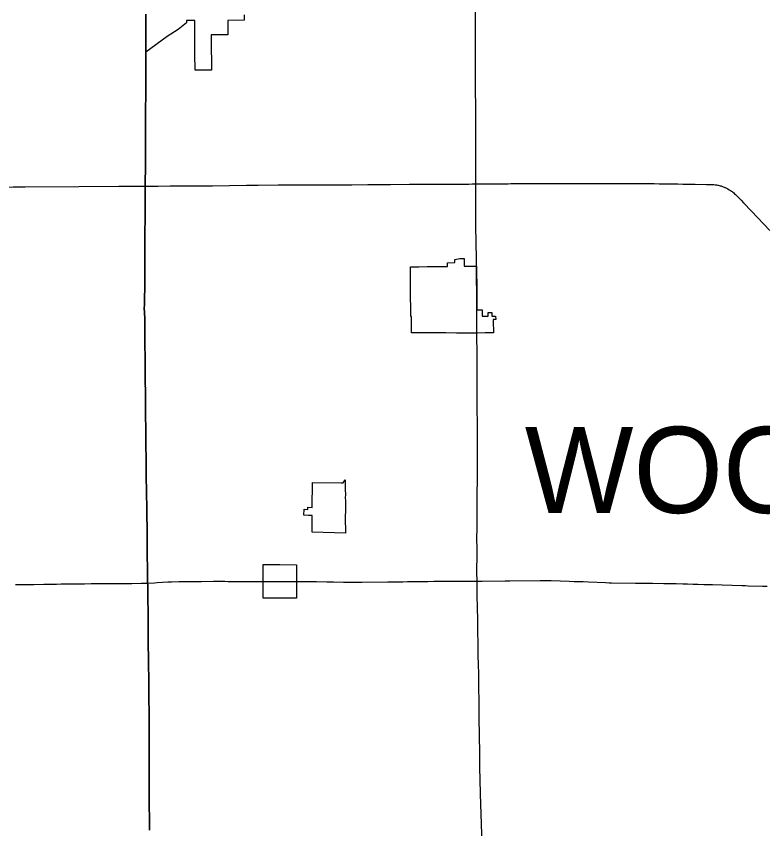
# Model space of a CAD drawing. Extents: x -786946 to -767280, y 417139 to 426807.
# Drawn here: x -778504 to -776473, y 420527 to 422738 of the extents above; entities that cross this region are included whole.
import ezdxf

# ---------------------------------------------------------------- set-up
doc = ezdxf.new("R2010")
doc.units = 0
for name, color, linetype in [('DV_X_Corp_Line', 7, 'Continuous'), ('DV_X_County_Line', 7, 'Continuous'), ('GM_X_State_Route', 7, 'Continuous'), ('SH_Text', 7, 'Continuous')]:
    doc.layers.add(name, color=color, linetype=linetype)

msp = doc.modelspace()

# ---------------------------------------------------------------- linework, layer by layer
at = {"layer": 'DV_X_Corp_Line'}
msp.add_lwpolyline([(-777883.9, 422742.2), (-777883.9, 422736.7), (-777883.9, 422735.1), (-777883.9, 422733.5), (-777883.9, 422732.7), (-777883.9, 422732), (-777883.8, 422727.2), (-777928.6, 422727.1), (-777928.4, 422715.6), (-777928.2, 422688), (-777973.6, 422688), (-777973.6, 422687.1), (-777973.5, 422679.6), (-777973.5, 422678), (-777973.5, 422673.9), (-777973.5, 422669.6), (-777973.4, 422665.3), (-777973.4, 422658.9), (-777973.5, 422656), (-777973.4, 422652.8), (-777973.4, 422649.5), (-777973.4, 422646.6), (-777973.4, 422645.1), (-777973.3, 422640.6), (-777973.3, 422636.7), (-777973.3, 422634.9), (-777973.2, 422630.4), (-777973.1, 422612.5), (-777973.1, 422605.3), (-777973, 422602.5), (-777973, 422591.4), (-778017.2, 422591.3), (-778017.8, 422636), (-778017.9, 422653.9), (-778018.2, 422679.3), (-778018.3, 422681.7), (-778018.3, 422700.5), (-778018.3, 422726.5), (-778035.9, 422726.5), (-778040.5, 422726.3), (-778040.7, 422720.4), (-778063.4, 422702.2), (-778093.9, 422683.4), (-778151.7, 422640.5), (-778151.7, 422643.7), (-778151.6, 422650.5), (-778151.6, 422660), (-778151.6, 422665.3), (-778151.6, 422670), (-778151.5, 422676.7), (-778151.5, 422683.3), (-778151.6, 422687.8), (-778151.7, 422697.1), (-778151.6, 422701.1), (-778151.6, 422711.3), (-778151.6, 422715.1), (-778151.7, 422722.3), (-778151.7, 422738.2)], dxfattribs=at)
for points in [[(-777285.3, 422057.8), (-777284.9, 422057.9), (-777282.3, 422057.9), (-777278.4, 422057.9), (-777252.3, 422058.1), (-777251.5, 422058.1), (-777251.4, 422035.4), (-777251.4, 422035.1), (-777251.2, 422012.2), (-777250.7, 421939.5), (-777236.6, 421939.6), (-777236.5, 421922.1), (-777228.2, 421922.1), (-777219.7, 421922.2), (-777219.8, 421932.3), (-777213.5, 421932.5), (-777210.2, 421932.5), (-777210.2, 421922.3), (-777206.4, 421922.3), (-777206, 421922.4), (-777199.6, 421922.4), (-777199.5, 421913.3), (-777199.5, 421912.7), (-777205.9, 421912.7), (-777205.9, 421909.8), (-777205.5, 421876.9), (-777227.6, 421876.5), (-777227.9, 421876.5), (-777248.9, 421875.6), (-777249.9, 421875.6), (-777250.3, 421875.6), (-777250.5, 421875.6), (-777260.3, 421875.7), (-777260.7, 421875.7), (-777272.3, 421875.8), (-777272.7, 421875.8), (-777294.6, 421876.1), (-777295, 421876.1), (-777305.8, 421876.2), (-777306.2, 421876.2), (-777334.8, 421876.5), (-777339.5, 421876.5), (-777339.8, 421876.5), (-777381.6, 421876.4), (-777385.6, 421876.4), (-777389.3, 421876.4), (-777399, 421876.3), (-777428.6, 421876.3), (-777428.6, 421876.7), (-777428.7, 421898.8), (-777428.8, 421905.7), (-777428.8, 421907.1), (-777428.8, 421913.5), (-777428.8, 421915.3), (-777428.9, 421916.3), (-777428.9, 421921.5), (-777430.5, 421921.5), (-777430.6, 421930.8), (-777430.7, 421937.3), (-777430.7, 421940.4), (-777430.7, 421941.8), (-777430.8, 421952.5), (-777431, 421966.3), (-777431.5, 422011.4), (-777431.5, 422019.1), (-777431.5, 422019.8), (-777431.5, 422024.9), (-777431.5, 422027.4), (-777431.5, 422031), (-777431.6, 422056.3), (-777427.5, 422056.3), (-777409, 422056.6), (-777386.4, 422056.8), (-777367.1, 422057), (-777347.9, 422057.2), (-777347.6, 422057.2), (-777341.8, 422057.3), (-777330.5, 422057.4), (-777330.5, 422067.5), (-777310.4, 422067.7), (-777310.4, 422076), (-777296.9, 422078.8), (-777296.9, 422079), (-777286, 422079.1), (-777285.2, 422079), (-777285.2, 422076.4), (-777285, 422062.9), (-777285, 422060.1), (-777285, 422059.6), (-777285, 422059.1), (-777285.1, 422058.7), (-777285.2, 422058.3)], [(-777608.3, 421331.9), (-777698.5, 421334), (-777698.6, 421344.4), (-777698.7, 421352.9), (-777698.9, 421364.7), (-777699, 421370.2), (-777699.3, 421379.7), (-777702.7, 421379.8), (-777708.8, 421380), (-777721.2, 421380.2), (-777720.8, 421396.6), (-777710.7, 421396.4), (-777710.6, 421402), (-777698.9, 421401.6), (-777698.2, 421469.6), (-777620.3, 421468.4), (-777614.2, 421468.2), (-777608.7, 421476.8), (-777608.7, 421469.8), (-777608.7, 421458.7), (-777608.7, 421449.3), (-777608.6, 421436.5), (-777608.7, 421427.6), (-777608.6, 421420.9), (-777608.6, 421399.2), (-777608.6, 421386.5), (-777608.7, 421382), (-777608.8, 421378), (-777608.8, 421377.6), (-777608.9, 421375.9), (-777608.7, 421360.3), (-777608.5, 421347)], [(-777832.1, 421154.5), (-777831.9, 421199.9), (-777832.6, 421235.3), (-777832.4, 421246.3), (-777786.8, 421246.1), (-777741.6, 421245.7), (-777741.5, 421227.2), (-777741.8, 421200.3), (-777741.5, 421199.1), (-777741.4, 421155), (-777787, 421154.8)]]:
    msp.add_lwpolyline(points, close=True, dxfattribs=at)
at = {"layer": 'DV_X_County_Line'}
for points in [[(-778151.7, 422743.9), (-778151.7, 422738.1), (-778151.6, 422722.2), (-778151.6, 422715), (-778151.6, 422711.2), (-778151.6, 422701), (-778151.6, 422697), (-778151.5, 422687.7), (-778151.5, 422683.2), (-778151.5, 422676.6), (-778151.5, 422669.9), (-778151.5, 422665.2), (-778151.5, 422659.9), (-778151.6, 422650.4), (-778151.7, 422640.4), (-778151.7, 422636.2), (-778151.7, 422633.9), (-778151.6, 422627.8), (-778151.6, 422617.2), (-778151.6, 422611.8), (-778151.6, 422607.5), (-778151.6, 422601.2), (-778151.6, 422595.5), (-778151.6, 422589.5), (-778151.7, 422582), (-778151.7, 422575.4), (-778151.7, 422565.3), (-778151.8, 422557.8), (-778151.8, 422549.8), (-778151.8, 422541.1), (-778151.8, 422529.5), (-778151.8, 422524.6), (-778151.9, 422520.8), (-778151.9, 422513.7), (-778151.9, 422509.1), (-778152, 422500.3), (-778152.1, 422496.4), (-778152.1, 422493.1), (-778152.1, 422485), (-778152.1, 422477.2), (-778152.2, 422471.6), (-778152.2, 422466.9), (-778152.3, 422462.4), (-778152.3, 422455.5), (-778152.5, 422449.6), (-778152.6, 422440.7), (-778152.6, 422429.6), (-778152.7, 422419), (-778152.7, 422409), (-778152.6, 422399), (-778152.6, 422386.7), (-778152.6, 422382.9), (-778152.5, 422374.5), (-778152.5, 422365.4), (-778152.5, 422362.8), (-778152.6, 422352.8), (-778152.6, 422343.3), (-778152.7, 422330.5), (-778152.8, 422310.5), (-778152.9, 422302.2), (-778153.1, 422298.3), (-778153.2, 422293.3), (-778153.3, 422281), (-778153.3, 422277.1), (-778153.3, 422275.7), (-778153.2, 422274.4), (-778153.4, 422248.8), (-778153.4, 422238.8), (-778153.6, 422217.6), (-778153.6, 422204.8), (-778153.6, 422194.2), (-778153.6, 422182), (-778153.8, 422154.8), (-778154, 422136.9), (-778154.1, 422107.5), (-778154, 422095.8), (-778154.2, 422067.7), (-778154.2, 422056), (-778154.1, 422047.1), (-778154.2, 422038.2), (-778154.3, 422031.5), (-778154.5, 422013.2), (-778154.6, 421993.7), (-778154.7, 421977.6), (-778154.8, 421962), (-778154.8, 421956.4), (-778154.9, 421953.1), (-778155.1, 421950.9), (-778155.3, 421949.2), (-778155.6, 421947.6), (-778156, 421946.1), (-778154.2, 421915.9), (-778153.4, 421738.1), (-778153.1, 421736.1), (-778152.9, 421734.7), (-778152.8, 421733.2), (-778152.9, 421731.6), (-778152.8, 421727.2), (-778152.6, 421708.9), (-778152.5, 421695), (-778152.4, 421689.4), (-778152.3, 421676.6), (-778152.2, 421668.3), (-778152.1, 421661.1), (-778152.1, 421657.2), (-778152, 421643.8), (-778152, 421636.6), (-778151.9, 421630.5), (-778151.9, 421624.4), (-778151.8, 421620.5), (-778151.7, 421610.4), (-778151.7, 421605.4), (-778151.6, 421599.3), (-778151.6, 421590.4), (-778151.4, 421584.9), (-778151.1, 421564.3), (-778151.1, 421557.8), (-778151.1, 421554.8), (-778151, 421550.9), (-778151, 421540.4), (-778150.9, 421527), (-778150.7, 421510.3), (-778150.6, 421500.3), (-778150.3, 421485.3), (-778150.2, 421472.5), (-778150, 421459.2), (-778149.9, 421449.2), (-778149.7, 421435.8), (-778149, 421404.7), (-778148.8, 421386.4), (-778148.6, 421380.4), (-778148.6, 421380.2), (-778148.5, 421374.1), (-778148.4, 421366.3), (-778148.3, 421357.5), (-778148.3, 421352.4), (-778148.2, 421346.3), (-778148.1, 421333.5), (-778148.1, 421327.4), (-778148, 421323), (-778147.8, 421310.8), (-778147.6, 421284.1), (-778147.5, 421256.3), (-778147.4, 421251.3), (-778147.4, 421242.9), (-778147.3, 421230.7), (-778147.2, 421225.1), (-778147.1, 421215.7), (-778147, 421200.7), (-778146.9, 421197.3), (-778146.9, 421196.8), (-778146.7, 421195.2), (-778146.6, 421194), (-778146.4, 421192.4), (-778146.3, 421189.6), (-778146.2, 421179.6), (-778146.1, 421168.5), (-778146, 421159), (-778146, 421153.5), (-778145.9, 421146.2), (-778145.7, 421137.4), (-778145.6, 421131.8), (-778145.2, 421107.3), (-778145, 421084.6), (-778145, 421071.2), (-778145, 421061.2), (-778144.9, 421045.1), (-778144.9, 421032.9), (-778144.9, 421020.1), (-778144.9, 421017.1), (-778144.8, 421015.1), (-778144.8, 421012.9), (-778144.7, 421006.7), (-778144.4, 420990.6), (-778144.3, 420985.1), (-778144.2, 420975.1), (-778144, 420959.5), (-778143.7, 420948.4), (-778143.5, 420932.3), (-778143.3, 420926.2), (-778143.2, 420916.7), (-778143, 420906.2), (-778143, 420900.1), (-778142.9, 420888.4), (-778142.9, 420868.4), (-778142.8, 420857.3), (-778142.7, 420839.5), (-778142.6, 420836), (-778142.5, 420830.9), (-778142.6, 420823.7), (-778142.5, 420819.5), (-778142.5, 420811.2), (-778142.4, 420804.8), (-778142.4, 420794.5), (-778142.4, 420789), (-778142.4, 420781.2), (-778142.3, 420772.6), (-778142.3, 420764), (-778142.2, 420753.1), (-778142.2, 420741.7), (-778142.1, 420736.7), (-778142.2, 420725.4), (-778142.2, 420719.2), (-778142.3, 420707.6), (-778142.3, 420701.2), (-778142.3, 420680.6), (-778142.3, 420666.5), (-778142.3, 420659.5), (-778142.3, 420657.6), (-778142.3, 420656.1), (-778142.3, 420655.4), (-778142.3, 420648.4), (-778142.3, 420637), (-778142.4, 420622.9), (-778142.3, 420611.5), (-778142.3, 420601.2), (-778142.1, 420588.2), (-778142, 420577.3), (-778141.9, 420567.4), (-778141.9, 420559.3), (-778141.7, 420554.6), (-778141.7, 420552.6), (-778141.6, 420549.3), (-778141.6, 420543.5), (-778141.5, 420535.4), (-778141.4, 420523.8)], [(-778141.4, 420523.8), (-778141.5, 420535.4), (-778141.6, 420543.5), (-778141.6, 420549.3), (-778141.7, 420552.6), (-778141.7, 420554.6), (-778141.9, 420559.3), (-778141.9, 420567.4), (-778142, 420577.3), (-778142.1, 420588.2), (-778142.3, 420601.2), (-778142.3, 420611.5), (-778142.4, 420622.9), (-778142.3, 420637), (-778142.3, 420648.4), (-778142.3, 420655.4), (-778142.3, 420656.1), (-778142.3, 420657.6), (-778142.3, 420659.5), (-778142.3, 420666.5), (-778142.3, 420680.6), (-778142.3, 420701.2), (-778142.3, 420707.6), (-778142.2, 420719.2), (-778142.2, 420725.4), (-778142.1, 420736.7), (-778142.2, 420741.7), (-778142.2, 420753.1), (-778142.3, 420764), (-778142.3, 420772.6), (-778142.4, 420781.2), (-778142.4, 420789), (-778142.4, 420794.5), (-778142.4, 420804.8), (-778142.5, 420811.2), (-778142.5, 420819.5), (-778142.6, 420823.7), (-778142.5, 420830.9), (-778142.6, 420836), (-778142.7, 420839.5), (-778142.8, 420857.3), (-778142.9, 420868.4), (-778142.9, 420888.4), (-778143, 420900.1), (-778143, 420906.2), (-778143.2, 420916.7), (-778143.3, 420926.2), (-778143.5, 420932.3), (-778143.7, 420948.4), (-778144, 420959.5), (-778144.2, 420975.1), (-778144.3, 420985.1), (-778144.4, 420990.6), (-778144.7, 421006.7), (-778144.8, 421012.9), (-778144.8, 421015.1), (-778144.9, 421017.1), (-778144.9, 421020.1), (-778144.9, 421032.9), (-778144.9, 421045.1), (-778145, 421061.2), (-778145, 421071.2), (-778145, 421084.6), (-778145.2, 421107.3), (-778145.6, 421131.8), (-778145.7, 421137.4), (-778145.9, 421146.2), (-778146, 421153.5), (-778146, 421159), (-778146.1, 421168.5), (-778146.2, 421179.6), (-778146.3, 421189.6), (-778146.4, 421192.4), (-778146.6, 421194), (-778146.7, 421195.2), (-778146.9, 421196.8), (-778146.9, 421197.3), (-778147, 421200.7), (-778147.1, 421215.7), (-778147.2, 421225.1), (-778147.3, 421230.7), (-778147.4, 421242.9), (-778147.4, 421251.3), (-778147.5, 421256.3), (-778147.6, 421284.1), (-778147.8, 421310.8), (-778148, 421323), (-778148.1, 421327.4), (-778148.1, 421333.5), (-778148.2, 421346.3), (-778148.3, 421352.4), (-778148.3, 421357.5), (-778148.4, 421366.3), (-778148.5, 421374.1), (-778148.6, 421380.2), (-778148.6, 421380.4), (-778148.8, 421386.4), (-778149, 421404.7), (-778149.7, 421435.8), (-778149.9, 421449.2), (-778150, 421459.2), (-778150.2, 421472.5), (-778150.3, 421485.3), (-778150.6, 421500.3), (-778150.7, 421510.3), (-778150.9, 421527), (-778151, 421540.4), (-778151, 421550.9), (-778151.1, 421554.8), (-778151.1, 421557.8), (-778151.1, 421564.3), (-778151.4, 421584.9), (-778151.6, 421590.4), (-778151.6, 421599.3), (-778151.7, 421605.4), (-778151.7, 421610.4), (-778151.8, 421620.5), (-778151.9, 421624.4), (-778151.9, 421630.5), (-778152, 421636.6), (-778152, 421643.8), (-778152.1, 421657.2), (-778152.1, 421661.1), (-778152.2, 421668.3), (-778152.3, 421676.6), (-778152.4, 421689.4), (-778152.5, 421695), (-778152.6, 421708.9), (-778152.8, 421727.2), (-778152.9, 421731.6), (-778152.8, 421733.2), (-778152.9, 421734.7), (-778153.1, 421736.1), (-778153.4, 421738.1), (-778154.2, 421915.9), (-778156, 421946.1), (-778155.6, 421947.6), (-778155.3, 421949.2), (-778155.1, 421950.9), (-778154.9, 421953.1), (-778154.8, 421956.4), (-778154.8, 421962), (-778154.7, 421977.6), (-778154.6, 421993.7), (-778154.5, 422013.2), (-778154.3, 422031.5), (-778154.2, 422038.2), (-778154.1, 422047.1), (-778154.2, 422056), (-778154.2, 422067.7), (-778154, 422095.8), (-778154.1, 422107.5), (-778154, 422136.9), (-778153.8, 422154.8), (-778153.6, 422182), (-778153.6, 422194.2), (-778153.6, 422204.8), (-778153.6, 422217.6), (-778153.4, 422238.8), (-778153.4, 422248.8), (-778153.2, 422274.4), (-778153.3, 422275.7), (-778153.3, 422277.1), (-778153.3, 422281), (-778153.2, 422293.3), (-778153.1, 422298.3), (-778152.9, 422302.2), (-778152.8, 422310.5), (-778152.7, 422330.5), (-778152.6, 422343.3), (-778152.6, 422352.8), (-778152.5, 422362.8), (-778152.5, 422365.4), (-778152.5, 422374.5), (-778152.6, 422382.9), (-778152.6, 422386.7), (-778152.6, 422399), (-778152.7, 422409), (-778152.7, 422419), (-778152.6, 422429.6), (-778152.6, 422440.7), (-778152.5, 422449.6), (-778152.3, 422455.5), (-778152.3, 422462.4), (-778152.2, 422466.9), (-778152.2, 422471.6), (-778152.1, 422477.2), (-778152.1, 422485), (-778152.1, 422493.1), (-778152.1, 422496.4), (-778152, 422500.3), (-778151.9, 422509.1), (-778151.9, 422513.7), (-778151.9, 422520.8), (-778151.8, 422524.6), (-778151.8, 422529.5), (-778151.8, 422541.1), (-778151.8, 422549.8), (-778151.8, 422557.8), (-778151.7, 422565.3), (-778151.7, 422575.4), (-778151.7, 422582), (-778151.6, 422589.5), (-778151.6, 422595.5), (-778151.6, 422601.2), (-778151.6, 422607.5), (-778151.6, 422611.8), (-778151.6, 422617.2), (-778151.6, 422627.8), (-778151.7, 422633.9), (-778151.7, 422636.2), (-778151.7, 422640.4), (-778151.6, 422650.4), (-778151.5, 422659.9), (-778151.5, 422665.2), (-778151.5, 422669.9), (-778151.5, 422676.6), (-778151.5, 422683.2), (-778151.5, 422687.7), (-778151.6, 422697), (-778151.6, 422701), (-778151.6, 422711.2), (-778151.6, 422715), (-778151.6, 422722.2), (-778151.7, 422738.1), (-778151.7, 422743.9)]]:
    msp.add_lwpolyline(points, dxfattribs=at)
at = {"layer": 'GM_X_State_Route'}
msp.add_line((-777915.7, 421200.5), (-777903.4, 421200.4), dxfattribs=at)
for points in [[(-777253.8, 422462.2), (-777253.8, 422464.7), (-777253.9, 422473), (-777253.9, 422496.7), (-777254.1, 422533.7), (-777254.1, 422551.6), (-777254.2, 422576), (-777254.3, 422616.6), (-777254.2, 422636.3), (-777254.2, 422641.7), (-777254.2, 422675.4), (-777254.2, 422698.5), (-777254.3, 422731.3), (-777254.3, 422749.1)], [(-777251.5, 422058), (-777251.5, 422058), (-777251.6, 422070.5), (-777251.8, 422084.4), (-777252, 422090.5), (-777252, 422098.3), (-777252.2, 422102.4), (-777252.5, 422107.2), (-777252.6, 422110), (-777252.6, 422113), (-777252.6, 422120.6), (-777253.1, 422168.5), (-777253.5, 422203.5), (-777253.5, 422215.8), (-777253.6, 422254.2), (-777253.6, 422271.5), (-777253.5, 422281.9), (-777253.6, 422290.4), (-777253.6, 422297.1), (-777253.5, 422347.2), (-777253.5, 422351.7), (-777253.5, 422371.8), (-777253.5, 422395.7), (-777253.6, 422419.6), (-777253.6, 422450.8), (-777253.7, 422459.2), (-777253.8, 422462.2)], [(-778592.6, 422273.4), (-778512.4, 422274), (-778479.8, 422274.2), (-778333.4, 422274.8), (-778225, 422275.4), (-778181.7, 422275.8), (-778156.1, 422275.9), (-778153.3, 422275.8)], [(-778153.3, 422275.8), (-778149.5, 422275.9), (-778118.1, 422276.2), (-778085.3, 422276.3), (-778074.5, 422276.3), (-778065, 422276.5), (-778029.5, 422276.7), (-777982.3, 422276.9), (-777974.1, 422276.9), (-777970.1, 422277)], [(-777970.1, 422277), (-777877.2, 422278.4), (-777845.7, 422278.7), (-777791.7, 422279.2)], [(-777791.7, 422279.2), (-777775.6, 422279.3), (-777763.9, 422279.4), (-777741.9, 422279.4), (-777734.3, 422279.5), (-777727, 422279.5), (-777715.6, 422279.5), (-777665.3, 422279.5), (-777652.4, 422279.6), (-777618.5, 422279.6), (-777611.4, 422279.6), (-777604.6, 422279.6), (-777590.7, 422279.7), (-777547.7, 422280)], [(-777547.7, 422280), (-777543, 422280), (-777533.4, 422280.1), (-777524.1, 422280.1), (-777518.7, 422280.2), (-777502.8, 422280.3), (-777491.9, 422280.4), (-777486, 422280.5), (-777433.6, 422280.9)], [(-777433.6, 422280.9), (-777424.2, 422281), (-777417.6, 422280.9), (-777413.4, 422281), (-777408.9, 422281), (-777372.3, 422281), (-777363.9, 422281), (-777358.9, 422281), (-777343.7, 422281.1), (-777331.6, 422281.1), (-777311.5, 422281.3), (-777272.4, 422281.6), (-777263.7, 422281.8), (-777253.5, 422281.9)], [(-777253.5, 422281.9), (-777240.6, 422282), (-777235.3, 422282), (-777202.9, 422282.2), (-777181.6, 422282.5), (-777172.4, 422282.6), (-777165.4, 422282.6), (-777158.5, 422282.7), (-777151, 422282.8), (-777117.2, 422282.8), (-777083.4, 422283), (-777077.8, 422283), (-777073, 422283.1)], [(-777073, 422283.1), (-777064.4, 422283.2), (-777053.6, 422283.3), (-777023.6, 422283.1), (-777009, 422283.1), (-776986.8, 422282.9), (-776965.6, 422282.9), (-776947.7, 422282.8), (-776922.5, 422282.8), (-776912.7, 422282.8), (-776902.8, 422282.8), (-776889.4, 422282.8), (-776881.7, 422282.8), (-776875.8, 422282.7), (-776857.9, 422282.8), (-776851.5, 422282.9), (-776823.5, 422283), (-776818, 422283), (-776799.5, 422283), (-776784.1, 422283), (-776768.3, 422282.8), (-776754.3, 422282.6), (-776747.1, 422282.6), (-776721.6, 422282.3), (-776712, 422282.1), (-776703.7, 422282), (-776689.9, 422281.7), (-776667.6, 422281.3), (-776656.5, 422281.3), (-776625.9, 422280.7), (-776620.6, 422280.6)], [(-776620.6, 422280.6), (-776616.8, 422280.6), (-776611.6, 422280.5), (-776608.4, 422280.3), (-776605.6, 422280.1), (-776602.4, 422279.7), (-776599, 422279.2), (-776596, 422278.7), (-776593.8, 422278.3), (-776591.5, 422277.8), (-776588.9, 422277.1), (-776586.3, 422276.3), (-776584, 422275.6), (-776580.9, 422274.4), (-776578.2, 422273.3), (-776575.9, 422272.4)], [(-776575.9, 422272.4), (-776575.6, 422272.2), (-776574.8, 422271.8), (-776571.6, 422270.3), (-776567.4, 422268.2), (-776564, 422266.3), (-776560.2, 422263.9), (-776558.1, 422262.5), (-776556, 422261), (-776553.8, 422259.2), (-776551.7, 422257.5), (-776549.2, 422255.4), (-776547.1, 422253.4), (-776544.7, 422251), (-776541.6, 422247.9), (-776531.7, 422237.4), (-776525.2, 422230.7), (-776503.5, 422207.8), (-776453.5, 422155.4)], [(-777250.8, 421939.4), (-777250.9, 421967.3), (-777251.3, 422042.2), (-777251.5, 422058)], [(-777250.5, 421875.2), (-777250.5, 421878.8), (-777250.7, 421921.9), (-777250.7, 421929.9), (-777250.8, 421939.4)], [(-777244.3, 420840.6), (-777244.3, 420850.3), (-777244.2, 420857.6), (-777244.4, 420874.2), (-777245, 420910.9), (-777245.7, 420955.3), (-777246, 420968.1), (-777246.8, 421004.8), (-777246.9, 421012.6), (-777247, 421020.9), (-777248.1, 421075.3), (-777248.3, 421089.2), (-777249.1, 421135.9), (-777249.5, 421155.9), (-777250.1, 421186.5), (-777250.2, 421200.8), (-777250.3, 421206.5), (-777250.4, 421219.8), (-777250.4, 421242.1), (-777250.3, 421259.3), (-777250.3, 421273.7), (-777250.3, 421290.4), (-777250.4, 421315.4), (-777249.9, 421347.1), (-777249.7, 421362.1), (-777249.5, 421377.1), (-777249.5, 421380.9), (-777249.6, 421384.9), (-777249.5, 421409.4), (-777249.5, 421438.3), (-777249.2, 421477.8), (-777249.1, 421512.2), (-777249.1, 421538.4), (-777249.1, 421561.3), (-777249.2, 421575.6), (-777249.3, 421589.5), (-777249.3, 421610.1), (-777249.4, 421618.4), (-777249.4, 421632.3), (-777249.7, 421667.4), (-777249.8, 421694.6), (-777249.9, 421703), (-777249.9, 421709.6), (-777250, 421730.2), (-777250, 421741.5), (-777250, 421756.9), (-777249.9, 421769.7), (-777250, 421790.3), (-777250.1, 421809.7), (-777250.1, 421815.9), (-777250.5, 421873.2), (-777250.5, 421875.2)], [(-778505.9, 421191.8), (-778484.8, 421192), (-778479.9, 421192.1), (-778466.5, 421192.2), (-778456.6, 421192.3), (-778429.3, 421192.7), (-778394.9, 421193.2), (-778382.2, 421193.4), (-778363, 421193.6), (-778345.9, 421193.8), (-778326.2, 421194), (-778318.7, 421194.1), (-778300.4, 421194.2), (-778288.7, 421194.2), (-778274.3, 421194.3), (-778257.8, 421194.5), (-778228.3, 421194.7), (-778189.5, 421194.9), (-778164.6, 421195.1), (-778159.4, 421195.1), (-778146.7, 421195.3)], [(-778146.7, 421195.3), (-778128.3, 421196.8), (-778121.1, 421197.3), (-778106.2, 421198.1), (-778091.2, 421198.9), (-778081.3, 421199.2), (-778061.9, 421199.8), (-778054.1, 421200), (-778037.5, 421200.2), (-777999.9, 421200.4), (-777967.5, 421200.6), (-777947.2, 421200.6), (-777936.7, 421200.6)], [(-777936.7, 421200.6), (-777927.3, 421200.5), (-777915.7, 421200.5)], [(-777903.4, 421200.4), (-777889.6, 421200.4), (-777877.4, 421200.3), (-777875.5, 421200.2)], [(-777875.5, 421200.2), (-777860.8, 421200.1), (-777840.3, 421200), (-777832, 421199.9)], [(-777832, 421199.9), (-777831.9, 421199.9), (-777820.4, 421199.9), (-777817.1, 421199.9)], [(-777817.1, 421199.9), (-777806.6, 421199.9), (-777799.5, 421199.8), (-777796.7, 421199.8), (-777794, 421199.8), (-777788.6, 421199.8)], [(-777788.6, 421199.8), (-777786.3, 421199.8), (-777770.1, 421199.9), (-777754, 421200.1), (-777743.3, 421200.3), (-777741.8, 421200.3)], [(-777741.8, 421200.3), (-777736.6, 421200.3), (-777733.2, 421200.3), (-777702.9, 421200.2), (-777686.8, 421200.1), (-777659.1, 421199.3), (-777640.9, 421198.8), (-777613.2, 421198), (-777608.4, 421198), (-777563.9, 421198.4), (-777493.1, 421199.1), (-777452.1, 421199.5), (-777439.4, 421199.7), (-777431.1, 421199.7), (-777427.8, 421199.7), (-777410.6, 421199.9), (-777401.7, 421200.1), (-777395.1, 421200.2), (-777384, 421200.5), (-777367.4, 421200.7), (-777358, 421200.8), (-777349.2, 421201), (-777339.2, 421201.1), (-777333.1, 421201.2), (-777318.1, 421201.2), (-777301.5, 421201.1), (-777295.5, 421201.1), (-777250.2, 421200.8)], [(-777250.2, 421200.8), (-777247.8, 421200.8), (-777236.2, 421200.9), (-777173.7, 421201.7), (-777160.9, 421201.9), (-777078.4, 421202.9), (-777071.8, 421202.9), (-777067.3, 421202.8)], [(-777067.3, 421202.8), (-777048.6, 421202.4), (-776999.9, 421200.9), (-776985.5, 421200.4), (-776961.7, 421199.7), (-776946.7, 421199.1), (-776900.3, 421197.1), (-776890.9, 421196.8), (-776888.4, 421196.7), (-776884.2, 421196.6), (-776818.9, 421195.8), (-776781.8, 421195.4), (-776773, 421195.3), (-776742, 421194.9), (-776722, 421194.7), (-776711.5, 421194.6), (-776708.6, 421194.5), (-776690.5, 421194), (-776677.8, 421193.6), (-776662.3, 421193.1), (-776649, 421192.7), (-776633.5, 421192.3), (-776623.5, 421192), (-776609.7, 421191.6), (-776529.7, 421189.1), (-776520, 421188.8), (-776512.3, 421188.7), (-776473.6, 421187.5), (-776460.3, 421187.2)], [(-777241.7, 420652.8), (-777241.8, 420655.7), (-777242, 420661.2), (-777242.2, 420692.9), (-777242.5, 420712.8), (-777243, 420745.8), (-777243.4, 420768.4), (-777243.8, 420783.4), (-777244.2, 420826.1), (-777244.3, 420840.6)], [(-777235.1, 420205.2), (-777235.1, 420211.3), (-777235.1, 420213.8), (-777235.2, 420222.7), (-777236.1, 420268.2), (-777236.8, 420293.8), (-777236.9, 420300.8), (-777237.1, 420310.4), (-777237.2, 420324.8), (-777237.5, 420370.3), (-777237.6, 420388.1), (-777237.6, 420402.5), (-777237.6, 420424.2), (-777237.5, 420446.9), (-777237.3, 420469.2), (-777237.4, 420484.1), (-777237.4, 420502.5), (-777237.6, 420512.5), (-777240.7, 420622.4), (-777241, 420633.5), (-777241.7, 420650.7), (-777241.7, 420652.8)]]:
    msp.add_lwpolyline(points, dxfattribs=at)

# ---------------------------------------------------------------- texts
at = {"layer": 'SH_Text'}
msp.add_text('WOOD', height=234.38, dxfattribs=at).set_placement((-777120.4, 421386.5))

doc.saveas('drawing.dxf')
